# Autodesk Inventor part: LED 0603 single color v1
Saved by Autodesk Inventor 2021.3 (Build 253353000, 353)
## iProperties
Created: 2023-09
Part Number: LED 0603 single color v1
Material: Generic
Document SubType Name: Modeling
Designer: AdminForWorker
Density: 1 g/cm^3
Appearance: Default
Title: LED 0603 single color v1
Author: AdminForWorker
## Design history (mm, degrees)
feature "Body1"
feature "Body2"
feature "Body3"
feature "Body4"
feature "Body5"
body "Solid1"
body "Solid2"
body "Solid3"
body "Solid4"
body "Solid5"
